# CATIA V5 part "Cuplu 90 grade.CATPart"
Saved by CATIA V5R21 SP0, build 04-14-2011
Part number: Cupla 90
Bounding box of the stored display mesh (mm): x -35 to 35, y -34.808 to 220, z -20 to 234.808
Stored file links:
  C:\Users\MIRCEA\Desktop\PRRO\CATIAV5\Cuplu 90 grade.CATPart
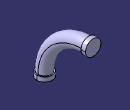
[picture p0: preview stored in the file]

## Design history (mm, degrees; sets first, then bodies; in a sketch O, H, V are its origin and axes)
Body1 (main body)
  Sketch1 on xy-plane, origin (0, 0, 0), H (1, 0, 0), V (0, 1, 0)
    circle A1 centre (0, 0) radius 30
    radius A1 = 30
  Sketch2 on yz-plane, origin (0, 0, 0), H (0, 1, 0), V (0, 0, 1)
    arc A1 centre (200, 0) radius 200 from (200, 200) to (0, 0) ccw
  Rib1: profile Sketch1, centre curve Sketch2
  Sketch3 on face of Rib1, origin (0, 0, 0), H (1, 0, 0), V (0, -1, 0)
    circle A1 centre (0, 0) radius 35
    radius A1 = 35
  Pad1: profile Sketch3, direction (0, 0, -1), length 20
  Sketch4 on face of Rib1, origin (0, 200, 0), H (-1, 0, 0), V (0, 0, 1)
    circle A1 centre (0, 200) radius 35
    radius A1 = 35
  Pad2: profile Sketch4, direction (0, 1, 0), length 20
